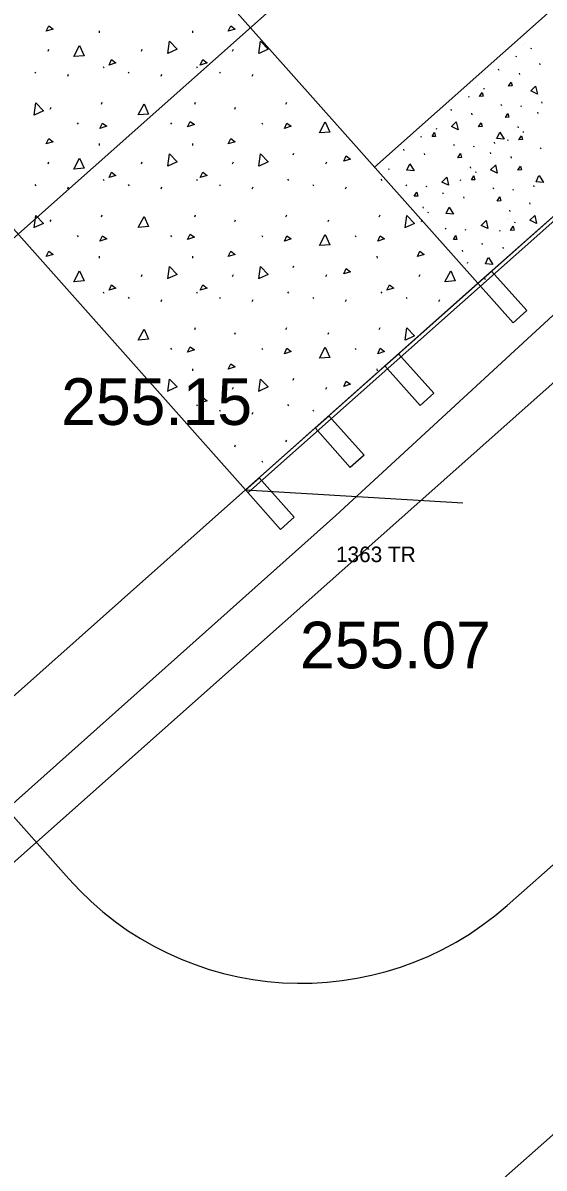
# Model space of a CAD drawing. Extents: x 49683 to 58852, y 49525 to 54803.
# Drawn here: x 53924.1 to 53957.6, y 51788.8 to 51862.4 of the extents above; entities that cross this region are included whole.
import ezdxf

# ---------------------------------------------------------------- set-up
doc = ezdxf.new("R2010")
doc.units = 0
for name, color, linetype in [('Level 11', 7, 'Continuous'), ('Level 13', 7, 'Continuous'), ('Level 15', 7, 'Continuous'), ('Level 18', 7, 'Continuous'), ('Level 19', 7, 'Continuous'), ('Level 20', 7, 'Continuous'), ('Level 27', 7, 'Continuous'), ('Level 32', 7, 'Continuous'), ('Level 61', 7, 'Continuous'), ('Level 8', 7, 'Continuous')]:
    doc.layers.add(name, color=color, linetype=linetype)

msp = doc.modelspace()

# ---------------------------------------------------------------- linework, layer by layer
at = {"layer": 'Level 11'}
for p, q in [((53944.235, 51830.768), (54450.301, 52297.6)), ((53245.856, 51207.553), (53944.235, 51830.768))]:
    msp.add_line(p, q, dxfattribs=at)
at = {"layer": 'Level 13'}
msp.add_line((53681.554, 51593.39), (53996.93, 51873.722), dxfattribs=at)
at = {"layer": 'Level 15'}
for p, q in [((53924.129, 51878.584), (53953.361, 51845.698)), ((53938.412, 51832.41), (53909.18, 51865.296)), ((53929.006, 51861.928), (53929.02, 51861.803)), ((53935.006, 51861.928), (53935.02, 51861.803)), ((53925.731, 51860.623), (53925.786, 51860.748)), ((53931.731, 51860.623), (53931.786, 51860.748)), ((53937.588, 51860.623), (53937.643, 51860.748)), ((53929.263, 51859.638), (53929.318, 51859.555)), ((53935.263, 51859.638), (53935.318, 51859.555)), ((53924.882, 51859.285), (53924.937, 51859.202)), ((53926.993, 51859.013), (53927.049, 51859.138)), ((53930.882, 51859.285), (53930.937, 51859.202)), ((53932.993, 51859.013), (53933.049, 51859.138)), ((53936.739, 51859.285), (53936.795, 51859.202)), ((53938.85, 51859.013), (53938.906, 51859.138)), ((53925.869, 51856.904), (53925.925, 51857.029)), ((53929.158, 51857.223), (53929.213, 51857.348)), ((53935.158, 51857.223), (53935.213, 51857.348)), ((53937.726, 51856.904), (53937.782, 51857.029)), ((53941.015, 51857.223), (53941.07, 51857.348)), ((53927.604, 51856.016), (53927.659, 51855.933)), ((53933.604, 51856.016), (53933.659, 51855.933)), ((53939.461, 51856.016), (53939.516, 51855.933)), ((53929.006, 51854.685), (53929.02, 51854.56)), ((53935.006, 51854.685), (53935.02, 51854.56)), ((53941.479, 51853.949), (53941.534, 51854.074)), ((53925.731, 51853.38), (53925.786, 51853.505)), ((53931.731, 51853.38), (53931.786, 51853.505)), ((53937.588, 51853.38), (53937.643, 51853.505)), ((53943.588, 51853.38), (53943.643, 51853.505)), ((53929.263, 51852.395), (53929.318, 51852.312)), ((53935.263, 51852.395), (53935.318, 51852.312)), ((53941.12, 51852.395), (53941.176, 51852.312)), ((53947.12, 51852.395), (53947.176, 51852.312)), ((53924.882, 51852.042), (53924.937, 51851.959)), ((53926.993, 51851.771), (53927.049, 51851.895)), ((53930.882, 51852.042), (53930.937, 51851.959)), ((53932.993, 51851.771), (53933.049, 51851.895)), ((53936.739, 51852.042), (53936.795, 51851.959)), ((53938.85, 51851.771), (53938.906, 51851.895)), ((53942.739, 51852.042), (53942.795, 51851.959)), ((53944.85, 51851.771), (53944.906, 51851.895)), ((53929.158, 51849.981), (53929.213, 51850.106)), ((53935.158, 51849.981), (53935.213, 51850.106)), ((53941.015, 51849.981), (53941.07, 51850.106)), ((53947.015, 51849.981), (53947.07, 51850.106)), ((53925.869, 51849.662), (53925.925, 51849.787)), ((53937.726, 51849.662), (53937.782, 51849.787)), ((53943.726, 51849.662), (53943.782, 51849.787)), ((53949.726, 51849.662), (53949.763, 51849.745)), ((53927.604, 51848.774), (53927.659, 51848.691)), ((53933.604, 51848.774), (53933.659, 51848.691)), ((53939.461, 51848.774), (53939.516, 51848.691)), ((53945.461, 51848.774), (53945.516, 51848.691)), ((53929.006, 51847.443), (53929.02, 51847.318)), ((53935.006, 51847.443), (53935.02, 51847.318)), ((53946.864, 51847.443), (53946.878, 51847.318)), ((53941.479, 51846.706), (53941.534, 51846.831)), ((53931.731, 51846.137), (53931.786, 51846.262)), ((53937.588, 51846.137), (53937.643, 51846.262)), ((53953.361, 51845.698), (53938.412, 51832.41)), ((53943.588, 51846.137), (53943.643, 51846.262)), ((53949.588, 51846.137), (53949.643, 51846.262)), ((53929.263, 51845.153), (53929.318, 51845.069)), ((53935.263, 51845.153), (53935.318, 51845.069)), ((53941.12, 51845.153), (53941.176, 51845.069)), ((53947.12, 51845.153), (53947.176, 51845.069)), ((53930.882, 51844.8), (53930.937, 51844.716)), ((53932.993, 51844.528), (53933.049, 51844.653)), ((53936.739, 51844.8), (53936.795, 51844.716)), ((53938.85, 51844.528), (53938.906, 51844.653)), ((53942.739, 51844.8), (53942.795, 51844.716)), ((53944.85, 51844.528), (53944.906, 51844.653)), ((53948.739, 51844.8), (53948.795, 51844.716)), ((53950.85, 51844.528), (53950.906, 51844.653)), ((53929.182, 51842.794), (53929.213, 51842.863)), ((53935.158, 51842.738), (53935.213, 51842.863)), ((53941.015, 51842.738), (53941.07, 51842.863)), ((53947.015, 51842.738), (53947.07, 51842.863)), ((53937.726, 51842.419), (53937.782, 51842.544)), ((53943.726, 51842.419), (53943.782, 51842.544)), ((53949.762, 51842.499), (53949.782, 51842.544)), ((53933.604, 51841.531), (53933.659, 51841.448)), ((53939.461, 51841.531), (53939.516, 51841.448)), ((53945.461, 51841.531), (53945.516, 51841.448)), ((53935.006, 51840.2), (53935.02, 51840.075)), ((53946.864, 51840.2), (53946.878, 51840.075)), ((53937.588, 51838.895), (53937.643, 51839.02)), ((53941.479, 51839.464), (53941.534, 51839.589)), ((53943.588, 51838.895), (53943.643, 51839.02)), ((53935.263, 51837.91), (53935.318, 51837.827)), ((53936.739, 51837.557), (53936.795, 51837.474)), ((53941.12, 51837.91), (53941.176, 51837.827)), ((53942.739, 51837.557), (53942.795, 51837.474)), ((53938.85, 51837.285), (53938.906, 51837.41)), ((53941.015, 51835.496), (53941.07, 51835.621)), ((53937.726, 51835.177), (53937.782, 51835.301)), ((53939.461, 51834.289), (53939.516, 51834.205)), ((53938.412, 51832.41), (53489.966, 51433.793)), ((53938.412, 51832.41), (53952.388, 51831.588))]:
    msp.add_line(p, q, dxfattribs=at)
for points in [[(53925.614, 51861.907), (53925.781, 51862.253), (53926.058, 51862.045), (53925.614, 51861.907)], [(53937.313, 51861.906), (53937.479, 51862.253), (53937.757, 51862.045), (53937.313, 51861.906)], [(53933.419, 51860.479), (53933.529, 51861.272), (53934.026, 51860.759), (53933.432, 51860.484)], [(53939.276, 51860.479), (53939.386, 51861.272), (53939.883, 51860.759), (53939.289, 51860.484)], [(53927.379, 51860.281), (53927.754, 51860.988), (53928.045, 51860.336), (53927.393, 51860.281)], [(53929.649, 51859.735), (53929.816, 51860.082), (53930.093, 51859.873), (53929.649, 51859.735)], [(53935.506, 51859.735), (53935.673, 51860.082), (53935.95, 51859.873), (53935.506, 51859.735)], [(53924.829, 51856.517), (53924.939, 51857.31), (53925.436, 51856.797), (53924.842, 51856.521)], [(53931.529, 51856.53), (53931.904, 51857.237), (53932.195, 51856.585), (53931.543, 51856.53)], [(53929.061, 51855.656), (53929.227, 51856.003), (53929.505, 51855.794), (53929.061, 51855.656)], [(53934.691, 51855.762), (53934.857, 51856.108), (53935.135, 51855.9), (53934.691, 51855.762)], [(53940.918, 51855.656), (53941.084, 51856.003), (53941.362, 51855.794), (53940.918, 51855.656)], [(53943.175, 51855.366), (53943.549, 51856.073), (53943.841, 51855.421), (53943.189, 51855.366)], [(53925.614, 51854.664), (53925.781, 51855.011), (53926.058, 51854.803), (53925.614, 51854.664)], [(53937.313, 51854.664), (53937.479, 51855.011), (53937.757, 51854.803), (53937.313, 51854.664)], [(53927.379, 51853.038), (53927.754, 51853.746), (53928.045, 51853.094), (53927.393, 51853.038)], [(53933.419, 51853.237), (53933.529, 51854.03), (53934.026, 51853.516), (53933.432, 51853.241)], [(53939.276, 51853.237), (53939.386, 51854.03), (53939.883, 51853.516), (53939.289, 51853.241)], [(53944.731, 51853.55), (53944.897, 51853.897), (53945.175, 51853.689), (53944.731, 51853.55)], [(53929.649, 51852.492), (53929.816, 51852.839), (53930.093, 51852.631), (53929.649, 51852.492)], [(53935.506, 51852.492), (53935.673, 51852.839), (53935.95, 51852.631), (53935.506, 51852.492)], [(53924.829, 51849.274), (53924.939, 51850.067), (53925.436, 51849.554), (53924.842, 51849.279)], [(53948.686, 51849.274), (53948.796, 51850.067), (53949.293, 51849.554), (53948.699, 51849.279)], [(53931.529, 51849.287), (53931.904, 51849.995), (53932.195, 51849.343), (53931.543, 51849.287)], [(53929.061, 51848.413), (53929.227, 51848.76), (53929.505, 51848.552), (53929.061, 51848.413)], [(53934.691, 51848.519), (53934.857, 51848.866), (53935.135, 51848.658), (53934.691, 51848.519)], [(53940.918, 51848.413), (53941.084, 51848.76), (53941.362, 51848.552), (53940.918, 51848.413)], [(53943.175, 51848.123), (53943.549, 51848.831), (53943.841, 51848.179), (53943.189, 51848.123)], [(53946.918, 51848.413), (53947.084, 51848.76), (53947.362, 51848.552), (53946.918, 51848.413)], [(53925.614, 51847.421), (53925.781, 51847.768), (53926.058, 51847.56), (53925.614, 51847.421)], [(53937.313, 51847.421), (53937.479, 51847.768), (53937.757, 51847.56), (53937.313, 51847.421)], [(53949.471, 51847.421), (53949.638, 51847.768), (53949.915, 51847.56), (53949.471, 51847.421)], [(53927.379, 51845.796), (53927.754, 51846.503), (53928.045, 51845.851), (53927.393, 51845.796)], [(53933.419, 51845.994), (53933.529, 51846.787), (53934.026, 51846.274), (53933.432, 51845.999)], [(53939.276, 51845.994), (53939.386, 51846.787), (53939.883, 51846.274), (53939.289, 51845.999)], [(53944.731, 51846.308), (53944.897, 51846.654), (53945.175, 51846.446), (53944.731, 51846.308)], [(53951.236, 51845.796), (53951.611, 51846.503), (53951.902, 51845.851), (53951.25, 51845.796)], [(53929.649, 51845.249), (53929.816, 51845.596), (53930.093, 51845.388), (53929.649, 51845.249)], [(53935.506, 51845.249), (53935.673, 51845.596), (53935.95, 51845.388), (53935.506, 51845.249)], [(53947.506, 51845.249), (53947.673, 51845.596), (53947.95, 51845.388), (53947.506, 51845.249)], [(53931.529, 51842.045), (53931.904, 51842.752), (53932.195, 51842.1), (53931.543, 51842.045)], [(53948.686, 51842.031), (53948.796, 51842.824), (53949.293, 51842.311), (53948.699, 51842.036)], [(53934.691, 51841.276), (53934.857, 51841.623), (53935.135, 51841.415), (53934.691, 51841.276)], [(53940.918, 51841.17), (53941.084, 51841.517), (53941.362, 51841.309), (53940.918, 51841.17)], [(53943.175, 51840.881), (53943.549, 51841.588), (53943.841, 51840.936), (53943.189, 51840.881)], [(53946.918, 51841.17), (53947.084, 51841.517), (53947.362, 51841.309), (53946.918, 51841.17)], [(53937.313, 51840.179), (53937.479, 51840.525), (53937.757, 51840.317), (53937.313, 51840.179)], [(53933.419, 51838.751), (53933.529, 51839.544), (53934.026, 51839.031), (53933.432, 51838.756)], [(53939.276, 51838.751), (53939.386, 51839.544), (53939.883, 51839.031), (53939.289, 51838.756)], [(53944.731, 51839.065), (53944.897, 51839.412), (53945.175, 51839.204), (53944.731, 51839.065)], [(53935.506, 51838.007), (53935.673, 51838.354), (53935.95, 51838.146), (53935.506, 51838.007)]]:
    msp.add_lwpolyline(points, dxfattribs=at)
at = {"layer": 'Level 18'}
for p, q in [((53927.062, 51807.399), (53889.003, 51850.215)), ((53955.241, 51805.689), (53959.122, 51809.112))]:
    msp.add_line(p, q, dxfattribs=at)
msp.add_arc((53942.01, 51820.687), 20, 221.63337, 311.41846, dxfattribs=at)
at = {"layer": 'Level 19'}
msp.add_line((52714.154, 50773.623), (54181.768, 52078.16), dxfattribs=at)
at = {"layer": 'Level 20'}
msp.add_line((53946.717, 51853.172), (54189.74, 52069.191), dxfattribs=at)
at = {"layer": 'Level 27'}
for p, q in [((53938.412, 51832.41), (54196.384, 52061.717)), ((53938.578, 51832.223), (54196.55, 52061.53)), ((53953.361, 51845.698), (53954.244, 51846.483)), ((53954.244, 51846.483), (53956.503, 51843.941)), ((53955.619, 51843.156), (53953.361, 51845.698)), ((53956.503, 51843.941), (53955.619, 51843.156)), ((53947.381, 51840.383), (53948.265, 51841.168)), ((53948.265, 51841.168), (53950.523, 51838.626)), ((53949.64, 51837.841), (53947.381, 51840.383)), ((53950.523, 51838.626), (53949.64, 51837.841)), ((53942.897, 51836.396), (53943.78, 51837.182)), ((53943.78, 51837.182), (53946.039, 51834.64)), ((53945.155, 51833.855), (53942.897, 51836.396)), ((53946.039, 51834.64), (53945.155, 51833.855)), ((53938.412, 51832.41), (53939.296, 51833.195)), ((53939.296, 51833.195), (53941.554, 51830.654)), ((53940.671, 51829.869), (53938.412, 51832.41)), ((53941.554, 51830.654), (53940.671, 51829.869))]:
    msp.add_line(p, q, dxfattribs=at)
at = {"layer": 'Level 61'}
msp.add_line((53517.816, 51402.461), (53967.758, 51799.396), dxfattribs=at)
at = {"layer": 'Level 8'}
for p, q in [((53956.395, 51861.097), (53956.395, 51861.097)), ((53956.268, 51860.989), (53956.268, 51860.989)), ((53956.836, 51860.781), (53956.772, 51860.799)), ((53955.861, 51860.263), (53955.797, 51860.281)), ((53957.324, 51859.836), (53957.349, 51859.749)), ((53954.67, 51859.49), (53954.696, 51859.403)), ((53956.006, 51859.216), (53956.032, 51859.129)), ((53953.217, 51858.402), (53953.217, 51858.402)), ((53953.344, 51858.51), (53953.344, 51858.51)), ((53953.785, 51858.194), (53953.721, 51858.212)), ((53952.81, 51857.676), (53952.746, 51857.694)), ((53951.619, 51856.903), (53951.645, 51856.816)), ((53954.903, 51857.14), (53954.842, 51857.198)), ((53956.19, 51857.068), (53956.126, 51857.087)), ((53957.195, 51856.703), (53957.221, 51856.616)), ((53957.455, 51857.365), (53957.481, 51857.277)), ((53950.293, 51855.923), (53950.293, 51855.923)), ((53952.955, 51856.629), (53952.981, 51856.542)), ((53950.166, 51855.815), (53950.166, 51855.815)), ((53950.735, 51855.607), (53950.67, 51855.626)), ((53953.361, 51845.698), (53964.572, 51855.663)), ((53955.742, 51855.615), (53955.742, 51855.615)), ((53955.869, 51855.723), (53955.869, 51855.723)), ((53955.921, 51855.785), (53955.946, 51855.697)), ((53956.311, 51855.407), (53956.246, 51855.426)), ((53949.759, 51855.089), (53949.695, 51855.107)), ((53951.852, 51854.553), (53951.791, 51854.611)), ((53953.139, 51854.481), (53953.075, 51854.5)), ((53954.404, 51854.778), (53954.43, 51854.69)), ((53955.335, 51854.889), (53955.271, 51854.907)), ((53948.568, 51854.316), (53948.594, 51854.229)), ((53949.904, 51854.042), (53949.93, 51853.955)), ((53954.145, 51854.116), (53954.17, 51854.029)), ((53955.48, 51853.843), (53955.506, 51853.755)), ((53957.428, 51854.353), (53957.367, 51854.411)), ((53947.684, 51853.02), (53947.62, 51853.039)), ((53952.691, 51853.028), (53952.691, 51853.028)), ((53952.818, 51853.136), (53952.818, 51853.136)), ((53952.87, 51853.198), (53952.895, 51853.11)), ((53952.284, 51852.302), (53952.22, 51852.32)), ((53953.26, 51852.82), (53953.196, 51852.839)), ((53948.802, 51851.966), (53948.741, 51852.024)), ((53950.089, 51851.894), (53950.025, 51851.913)), ((53951.094, 51851.53), (53951.119, 51851.442)), ((53954.378, 51851.766), (53954.317, 51851.824)), ((53955.665, 51851.694), (53955.601, 51851.713)), ((53956.929, 51851.991), (53956.955, 51851.903)), ((53952.43, 51851.256), (53952.455, 51851.168)), ((53956.67, 51850.876), (53956.695, 51850.789)), ((53949.819, 51850.611), (53949.845, 51850.523)), ((53950.209, 51850.233), (53950.145, 51850.252)), ((53955.395, 51850.411), (53955.421, 51850.323)), ((53955.216, 51849.788), (53955.216, 51849.788)), ((53955.344, 51849.896), (53955.344, 51849.896)), ((53955.785, 51849.58), (53955.721, 51849.598)), ((53951.327, 51849.18), (53951.266, 51849.237)), ((53952.614, 51849.107), (53952.55, 51849.126)), ((53954.809, 51849.061), (53954.745, 51849.08)), ((53952.344, 51847.824), (53952.37, 51847.736)), ((53953.619, 51848.289), (53953.644, 51848.202)), ((53954.955, 51848.015), (53954.98, 51847.928)), ((53952.734, 51846.993), (53952.67, 51847.011)), ((53953.852, 51845.939), (53953.791, 51845.996))]:
    msp.add_line(p, q, dxfattribs=at)
for points in [[(53955.498, 51858.637), (53955.563, 51858.389), (53955.332, 51858.375), (53955.498, 51858.637)], [(53957.072, 51858.385), (53957.187, 51857.863), (53956.758, 51858.069), (53957.065, 51858.379)], [(53953.631, 51857.978), (53953.696, 51857.73), (53953.465, 51857.716), (53953.631, 51857.978)], [(53951.97, 51856.092), (53952.084, 51855.571), (53951.655, 51855.777), (53951.963, 51856.086)], [(53953.568, 51856.027), (53953.633, 51855.779), (53953.402, 51855.765), (53953.568, 51856.027)], [(53955.294, 51856.624), (53955.359, 51856.375), (53955.128, 51856.362), (53955.294, 51856.624)], [(53950.58, 51855.391), (53950.645, 51855.143), (53950.414, 51855.129), (53950.58, 51855.391)], [(53954.766, 51855.423), (53955.052, 51854.973), (53954.578, 51855.019), (53954.762, 51855.415)], [(53956.156, 51855.191), (53956.221, 51854.943), (53955.99, 51854.93), (53956.156, 51855.191)], [(53952.243, 51854.037), (53952.308, 51853.788), (53952.077, 51853.775), (53952.243, 51854.037)], [(53948.984, 51853.388), (53949.27, 51852.937), (53948.796, 51852.984), (53948.98, 51853.38)], [(53954.495, 51853.306), (53954.609, 51852.784), (53954.18, 51852.99), (53954.488, 51853.3)], [(53956.093, 51853.24), (53956.158, 51852.992), (53955.927, 51852.978), (53956.093, 51853.24)], [(53951.365, 51852.528), (53951.479, 51852.006), (53951.05, 51852.212), (53951.358, 51852.522)], [(53953.105, 51852.604), (53953.17, 51852.356), (53952.939, 51852.343), (53953.105, 51852.604)], [(53957.291, 51852.637), (53957.577, 51852.186), (53957.103, 51852.233), (53957.287, 51852.629)], [(53949.426, 51851.555), (53949.491, 51851.307), (53949.26, 51851.293), (53949.426, 51851.555)], [(53954.768, 51851.25), (53954.833, 51851.002), (53954.602, 51850.988), (53954.768, 51851.25)], [(53951.509, 51850.601), (53951.795, 51850.15), (53951.321, 51850.197), (53951.505, 51850.593)], [(53957.02, 51850.065), (53957.134, 51849.544), (53956.705, 51849.75), (53957.013, 51850.059)], [(53953.89, 51849.741), (53954.005, 51849.22), (53953.575, 51849.426), (53953.883, 51849.735)], [(53955.63, 51849.364), (53955.695, 51849.116), (53955.464, 51849.102), (53955.63, 51849.364)], [(53951.951, 51848.768), (53952.016, 51848.52), (53951.785, 51848.506), (53951.951, 51848.768)], [(53954.034, 51847.36), (53954.32, 51846.91), (53953.847, 51846.956), (53954.03, 51847.352)]]:
    msp.add_lwpolyline(points, dxfattribs=at)

# ---------------------------------------------------------------- texts
at = {"layer": 'Level 32'}
for s, p in [('255.15', (53926.575, 51836.589)), ('255.07', (53941.922, 51820.937))]:
    msp.add_text(s, height=3, dxfattribs=at).set_placement(p)
at = {"layer": 'Level 61'}
msp.add_text('1363 TR', height=1, dxfattribs=at).set_placement((53944.235, 51827.768))

doc.saveas('drawing.dxf')
